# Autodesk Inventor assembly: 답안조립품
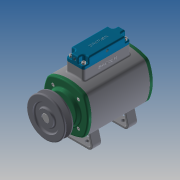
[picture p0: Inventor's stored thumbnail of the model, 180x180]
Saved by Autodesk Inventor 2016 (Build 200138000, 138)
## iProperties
Created: 2016-10
Part Number: 답안조립품
Document SubType Name: Assembly
Designer: Administrator
Author: Administrator
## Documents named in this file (18)
- D:\361007V1009\답안조립품.iam
- D:\361007V1009\361007V1009\본체.ipt
- D:\361007V1009\361007V1009\축.ipt
- D:\361007V1009\361007V1009\키 - 5 x 5 x 18.ipt
- D:\361007V1009\361007V1009\베어링 6203.ipt
- D:\361007V1009\361007V1009\오일실 17 30 8.ipt
- D:\361007V1009\361007V1009\멈춤나사 M4x5.ipt
- D:\361007V1009\361007V1009\V-벨트풀리.ipt
- D:\361007V1009\361007V1009\볼트 M4 x 12.ipt
- D:\361007V1009\361007V1009\앞커버.ipt
- D:\361007V1009\361007V1009\뒷커버.ipt
- D:\361007V1009\361007V1009\슬라이드.ipt
- D:\361007V1009\361007V1009\스프링1.ipt
- D:\361007V1009\361007V1009\스프링2.ipt
- D:\361007V1009\361007V1009\스프링3.ipt
- D:\361007V1009\361007V1009\헤더커버.ipt
- D:\361007V1009\361007V1009\부시.ipt
- D:\361007V1009\361007V1009\볼트 M4 x 16.ipt
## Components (4 placed, 3 different names)
1. 7-베어링 6203:1
2. V-벨트풀리:1
3. 7-베어링 6203:2
4. 헤더커버:1
